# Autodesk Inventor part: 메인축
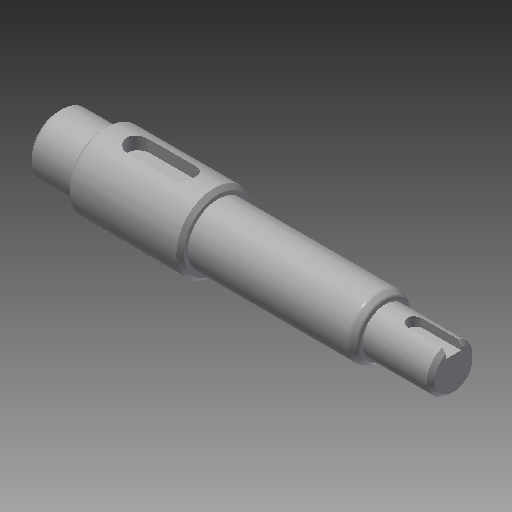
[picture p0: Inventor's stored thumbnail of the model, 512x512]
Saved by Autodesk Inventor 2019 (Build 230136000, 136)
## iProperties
Created: 2019-03
Part Number: 메인축
Material: 강철, 연강
Document SubType Name: Modeling
Designer: mduedu
Density: 1 g/cm^3
Appearance: 강철
Author: mduedu
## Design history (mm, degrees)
sketch "스케치1"
  geometry: L1 (0, 0)-(12, 0); L2 (12, 0)-(12, 8); L3 (12, 8)-(0, 8); L4 (0, 8)-(0, 0); L5 (12, 0)-(42, 0); L6 (42, 0)-(42, 10); L7 (42, 10)-(12, 10); L8 (12, 10)-(12, 0); L9 (42, 0)-(86, 0); L10 (86, 0)-(86, 8); L11 (86, 8)-(42, 8); L12 (42, 8)-(42, 0); L13 (86, 0)-(104, 0); L14 (104, 0)-(104, 6); L15 (104, 6)-(86, 6); L16 (86, 6)-(86, 0)
  constraints: 32 end point, 8 parallel, 4 horizontal, 4 perpendicular
  dimensions: "d0" = 16 diameter of L3 L1; "d2" = 20 diameter of L7 L5; "d3" = 16 diameter of L11 L9; "d4" = 12 diameter of L15 L13; "d5" = 12 distance of L2.end L3.end; "d6" = 30 distance of L6.end L7.end; "d7" = 86 distance between parallel lines of L10 L4; "d8" = 104 distance between parallel lines of L14 L4
revolve "회전1" sketch "스케치1" stored, may be unused: angle "d9" = 90 deg
node "작업 평면1"
sketch "스케치2" dims "d10" = 18
  geometry: L1 (6, -3)-(-6, -3); L2 (-6, -3)-(-6, 3); L3 (-6, 3)-(6, 3); L4 (6, 3)-(6, -3); L5 (15, 10)-(15, -10) reference; 3 further points
  constraints: 8 end point, 2 midpoint, 2 parallel, 2 vertical alignment, 1 horizontal, 1 horizontal alignment, 1 perpendicular, 4 other
  dimensions: "d12" = 6 distance between parallel lines of L3 L1; "d13" = 6 dimension on L5
extrude "돌출1" cut sketch "스케치2" distance "d14" = 3.5; taper "d15" = 0 deg
node "작업 평면2"
sketch "스케치3"
  geometry: L1 (-9, 6)-(-9, -6) reference; L2 (1, -2)-(-9, -2); L3 (1, 2)-(-9, 2); A1 r 2 centre (1, 0) between (1, -2) and (1, 2); 2 further points
  constraints: 4 end point, 2 point on circle, 2 point on line, 2 tangent, 1 centre point, 1 horizontal alignment, 1 midpoint, 1 parallel, 1 perpendicular
  dimensions: "d16" = 12 dimension on A1 L1; "d17" = 4 distance between parallel lines of L3 L2
extrude "돌출2" cut sketch "스케치3" distance "d18" = 2.5; taper "d19" = 0 deg
chamfer "모따기1" distance "d20" = 1; stored, may be unused: second distance "d21" = 2, angle "d22" = 45 deg
chamfer "모따기2" distance "d23" = 1; stored, may be unused: second distance "d24" = 2, angle "d25" = 45 deg
chamfer "모따기3" distance "d26" = 1.73; stored, may be unused: second distance "d27" = 2, angle "d28" = 30 deg
fillet "모깎기2" dims "d31" = 1, "d32" = 2
node "솔리드1"
